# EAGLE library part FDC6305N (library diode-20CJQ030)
Fairchild's FDC6305N Dual N-Channel 2.5V Specified PowerTrenchTM MOSFET General Description: These N-Channel low threshold 2.5V specified MOSFETs are produced using Fairchild Semiconductor's advanced PowerTrench process that has been especially tailored to minimize on-state resistance and yet maintain low gate charge for superior switching performance. Features: 2.7 A, 20 V. RDS(ON) = 0.08Ohm @ VGS = 4.5 V RDS(ON) = 0.12Ohm @ VGS = 2.5 V Low gate charge (3.5nC typical). Fast switching speed. High performance trench technology for extremely low RDS(ON). SuperSOTTM-6 package: small footprint (72% smaller than standard SO-8); low profile (1mm thick). Applications: Load switch DC/DC converter Motor driving Please send any comments to: messi@users.sourceforge.net
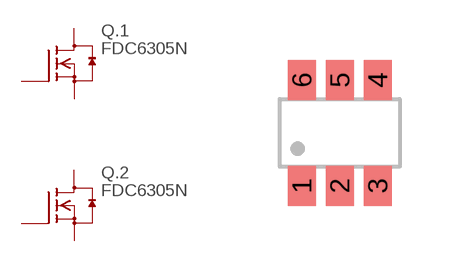
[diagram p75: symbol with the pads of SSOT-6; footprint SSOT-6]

Designator prefix Q; gates .1=IGFET-3-N-CH .2=IGFET-3-N-CH

## FDC6305N  [SSOT-6]
1  .1:G  pas
2  .2:S  pas
3  .2:G  pas
4  .2:D  pas
5  .1:S  pas
6  .1:D  pas

## Footprint SSOT-6 (pad centres in mm)
SuperSOT-6 (FS PKG Code 31, 33) E.g.: FDC6305N Dual N-Channel 2.5V Specified PowerTrench MOSFET
smd 0.7 x 1: 1 -0.95,-1.325; 2 0,-1.325; 3 0.95,-1.325; 4 0.95,1.325; 5 0,1.325; 6 -0.95,1.325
